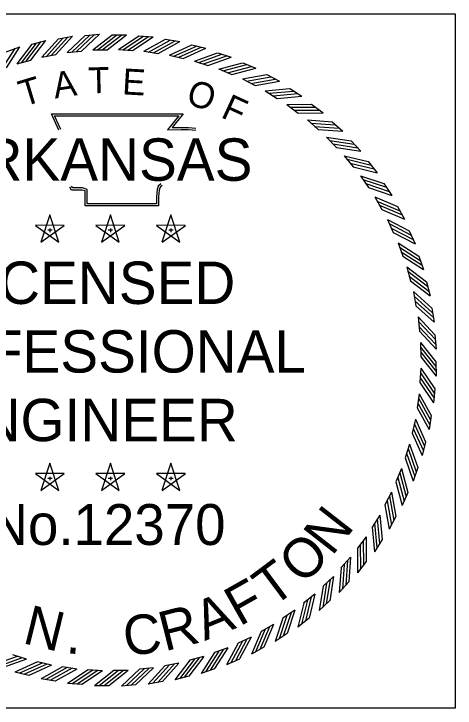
# Model space of a CAD drawing. Extents: x 0 to 1228740, y 0 to 152440.
# Drawn here: x 40.635 to 42.383, y 22.633 to 25.383 of the extents above; entities that cross this region are included whole.
import ezdxf

# ---------------------------------------------------------------- set-up
doc = ezdxf.new("R2010")
doc.units = 0
doc.layers.add('R_No Plot', color=7, linetype='Continuous')
doc.layers.add('STAMP_TNC', color=7, linetype='Continuous')

msp = doc.modelspace()

# ---------------------------------------------------------------- linework, layer by layer
at = {"layer": 'R_No Plot'}
msp.add_lwpolyline([(39.6327, 25.3826), (42.3827, 25.3826), (42.3827, 22.6326), (39.6327, 22.6326)], close=True, dxfattribs=at)
at = {"layer": 'STAMP_TNC'}
for p, q in [((40.9171, 25.2968), (40.9734, 25.302)), ((40.7068, 25.2628), (40.7615, 25.2772)), ((40.8113, 25.2841), (40.867, 25.2939)), ((41.0242, 25.2999), (41.0808, 25.2999)), ((41.1301, 25.2957), (41.1865, 25.2915)), ((41.2358, 25.282), (41.2917, 25.2732)), ((40.6045, 25.2329), (40.6578, 25.2517)), ((41.3401, 25.2595), (41.395, 25.2462)), ((40.7457, 25.2115), (40.8016, 25.2213)), ((40.8458, 25.2298), (40.9022, 25.235)), ((40.947, 25.2397), (41.0037, 25.2397)), ((41.0488, 25.2413), (41.1053, 25.2372)), ((41.1503, 25.2345), (41.2062, 25.2257)), ((41.2508, 25.2193), (41.3059, 25.2059)), ((41.4421, 25.2286), (41.4957, 25.2107)), ((40.6475, 25.1849), (40.7023, 25.1994)), ((41.3498, 25.1959), (41.4036, 25.178)), ((41.4466, 25.1644), (41.4987, 25.1421)), ((41.5412, 25.1894), (41.5932, 25.1671)), ((41.6367, 25.142), (41.6867, 25.1156)), ((41.5403, 25.125), (41.5904, 25.0984)), ((41.728, 25.087), (41.7756, 25.0565)), ((41.6306, 25.0779), (41.6783, 25.0474)), ((41.7166, 25.0236), (41.7616, 24.9892)), ((41.8144, 25.0246), (41.8594, 24.9903)), ((41.7978, 24.9624), (41.8399, 24.9244)), ((41.8954, 24.9553), (41.9374, 24.9174)), ((41.8737, 24.8947), (41.9125, 24.8533)), ((41.9704, 24.8796), (42.0091, 24.8383)), ((41.9438, 24.8209), (41.979, 24.7765)), ((42.0389, 24.7979), (42.074, 24.7536)), ((42.0075, 24.7416), (42.039, 24.6945)), ((42.1004, 24.7108), (42.1318, 24.6637)), ((42.0645, 24.6574), (42.0919, 24.6078)), ((42.1545, 24.619), (42.1819, 24.5695)), ((40.7771, 24.5864), (40.7417, 24.4779)), ((40.8123, 24.4779), (40.7772, 24.5865)), ((41.017, 24.5864), (40.9816, 24.4779)), ((41.0522, 24.4779), (41.017, 24.5865)), ((41.2568, 24.5864), (41.2215, 24.4779)), ((41.2921, 24.4779), (41.2569, 24.5865)), ((42.1143, 24.5686), (42.1375, 24.517)), ((40.8341, 24.545), (40.72, 24.5451)), ((40.7201, 24.545), (40.8124, 24.4778)), ((40.7419, 24.4779), (40.8343, 24.545)), ((40.7772, 24.5328), (40.7772, 24.5185)), ((41.074, 24.545), (40.9598, 24.5451)), ((40.9599, 24.545), (41.0522, 24.4778)), ((40.9817, 24.4779), (41.0741, 24.545)), ((41.0171, 24.5328), (41.0171, 24.5185)), ((41.3139, 24.545), (41.1997, 24.5451)), ((41.1998, 24.545), (41.2921, 24.4778)), ((41.2216, 24.4779), (41.314, 24.545)), ((41.2569, 24.5328), (41.2569, 24.5185)), ((40.769, 24.5267), (40.7859, 24.5267)), ((41.0088, 24.5267), (41.0258, 24.5267)), ((41.2487, 24.5267), (41.2657, 24.5267)), ((42.2008, 24.5229), (42.224, 24.4714)), ((42.1566, 24.4761), (42.1755, 24.4227)), ((42.2391, 24.4234), (42.2579, 24.3701)), ((42.1911, 24.3804), (42.2055, 24.3256)), ((42.269, 24.3211), (42.2833, 24.2664)), ((42.2176, 24.2822), (42.2275, 24.2264)), ((42.2903, 24.2167), (42.3001, 24.161)), ((42.2359, 24.1822), (42.2411, 24.1257)), ((42.3029, 24.1108), (42.3081, 24.0545)), ((42.2459, 24.0809), (42.2464, 24.0242)), ((42.3068, 24.0043), (42.3073, 23.9478)), ((42.2475, 23.9792), (42.2433, 23.9227)), ((42.3019, 23.8978), (42.2977, 23.8414)), ((42.2407, 23.8777), (42.2319, 23.8217)), ((42.2881, 23.7921), (42.2793, 23.7363)), ((42.2255, 23.7771), (42.2121, 23.722)), ((42.2021, 23.6781), (42.1842, 23.6243)), ((42.2657, 23.6879), (42.2523, 23.633)), ((40.7771, 23.6029), (40.7417, 23.4944)), ((40.8123, 23.4944), (40.7772, 23.603)), ((41.017, 23.6029), (40.9816, 23.4944)), ((41.0522, 23.4944), (41.017, 23.603)), ((41.2568, 23.6029), (41.2215, 23.4944)), ((41.2921, 23.4944), (41.2569, 23.603)), ((42.1706, 23.5814), (42.1483, 23.5293)), ((42.2348, 23.5859), (42.2169, 23.5322)), ((40.8341, 23.5615), (40.72, 23.5616)), ((40.7201, 23.5615), (40.8124, 23.4943)), ((40.7419, 23.4944), (40.8343, 23.5615)), ((40.769, 23.5432), (40.7859, 23.5432)), ((40.7772, 23.5493), (40.7772, 23.535)), ((41.074, 23.5615), (40.9598, 23.5616)), ((40.9599, 23.5615), (41.0522, 23.4943)), ((40.9817, 23.4944), (41.0741, 23.5615)), ((41.0088, 23.5432), (41.0258, 23.5432)), ((41.0171, 23.5493), (41.0171, 23.535)), ((41.3139, 23.5615), (41.1997, 23.5616)), ((41.1998, 23.5615), (41.2921, 23.4943)), ((41.2216, 23.4944), (41.314, 23.5615)), ((41.2487, 23.5432), (41.2657, 23.5432)), ((41.2569, 23.5493), (41.2569, 23.535)), ((42.1311, 23.4876), (42.1046, 23.4375)), ((42.1955, 23.4868), (42.1733, 23.4348)), ((42.0841, 23.3974), (42.0536, 23.3497)), ((42.1482, 23.3913), (42.1218, 23.3413)), ((42.0298, 23.3114), (41.9954, 23.2663)), ((42.0932, 23.3), (42.0627, 23.2523)), ((41.9686, 23.2301), (41.9306, 23.1881)), ((42.0308, 23.2135), (41.9965, 23.1686)), ((41.9009, 23.1542), (41.8595, 23.1155)), ((41.9615, 23.1325), (41.9236, 23.0906)), ((41.8271, 23.0842), (41.7827, 23.049)), ((41.8857, 23.0576), (41.8445, 23.0189)), ((41.7478, 23.0204), (41.7007, 22.989)), ((41.6635, 22.9635), (41.6139, 22.9361)), ((41.804, 22.9891), (41.7597, 22.9539)), ((41.5748, 22.9137), (41.5231, 22.8904)), ((41.717, 22.9276), (41.6699, 22.8962)), ((41.4823, 22.8714), (41.4289, 22.8525)), ((41.6251, 22.8735), (41.5756, 22.8461)), ((40.6843, 22.8259), (40.6305, 22.8438)), ((41.3866, 22.8368), (41.3318, 22.8224)), ((41.5291, 22.8271), (41.4776, 22.804)), ((40.7833, 22.8025), (40.7282, 22.8159)), ((41.2884, 22.8103), (41.2326, 22.8005)), ((40.6941, 22.7622), (40.6391, 22.7756)), ((40.8839, 22.7873), (40.8279, 22.7961)), ((40.9854, 22.7805), (40.9289, 22.7846)), ((41.0871, 22.782), (41.0304, 22.7815)), ((41.1883, 22.792), (41.1319, 22.7868)), ((41.4296, 22.7889), (41.3763, 22.7701)), ((40.7983, 22.7398), (40.7424, 22.7486)), ((41.3273, 22.759), (41.2726, 22.7446)), ((40.904, 22.7261), (40.8476, 22.7303)), ((41.0105, 22.7212), (40.9539, 22.7206)), ((41.117, 22.725), (41.0607, 22.7198)), ((41.2229, 22.7377), (41.1672, 22.7279))]:
    msp.add_line(p, q, dxfattribs=at)
for points in [[(40.8834, 25.2334), (40.9547, 25.3004)], [(40.9022, 25.235), (40.9735, 25.302)], [(40.9848, 25.24), (41.062, 25.3001)], [(40.684, 25.1948), (40.7433, 25.2726)], [(40.7023, 25.1994), (40.7616, 25.2772)], [(40.7457, 25.2114), (40.8112, 25.2841)], [(40.7636, 25.2144), (40.8292, 25.287)], [(40.7829, 25.2182), (40.8484, 25.2909)], [(40.8015, 25.2213), (40.867, 25.294)], [(40.8457, 25.2297), (40.9171, 25.2967)], [(40.8639, 25.2312), (40.9352, 25.2982)], [(40.947, 25.2397), (41.0241, 25.2999)], [(40.9652, 25.2395), (41.0423, 25.2997)], [(41.0037, 25.2398), (41.0808, 25.3)], [(41.0487, 25.2413), (41.1301, 25.2956)], [(41.0668, 25.2398), (41.1482, 25.2941)], [(41.0864, 25.2388), (41.1678, 25.2931)], [(41.1052, 25.2372), (41.1866, 25.2916)], [(41.1502, 25.2345), (41.2358, 25.2819)], [(41.1681, 25.2315), (41.2537, 25.2789)], [(41.1876, 25.2288), (41.2732, 25.2763)], [(41.2062, 25.2257), (41.2918, 25.2732)], [(40.5874, 25.1632), (40.6401, 25.2457)], [(40.6052, 25.1693), (40.6579, 25.2518)], [(40.6475, 25.1849), (40.7068, 25.2627)], [(40.6651, 25.1893), (40.7244, 25.2672)], [(41.2508, 25.2193), (41.34, 25.2595)], [(41.2684, 25.2148), (41.3576, 25.255)], [(41.2876, 25.2106), (41.3768, 25.2508)], [(41.3059, 25.206), (41.3951, 25.2462)], [(41.3498, 25.1959), (41.442, 25.2286)], [(41.367, 25.19), (41.4592, 25.2227)], [(41.3858, 25.1842), (41.478, 25.2169)], [(41.4036, 25.178), (41.4958, 25.2108)], [(41.4465, 25.1643), (41.5411, 25.1893)], [(41.4631, 25.157), (41.5578, 25.182)], [(41.4814, 25.1497), (41.576, 25.1747)], [(41.4986, 25.1421), (41.5932, 25.1671)], [(41.5403, 25.1249), (41.6366, 25.142)], [(41.5563, 25.1163), (41.6526, 25.1334)], [(41.5738, 25.1075), (41.6702, 25.1246)], [(41.5904, 25.0985), (41.6867, 25.1156)], [(41.6305, 25.0779), (41.7279, 25.087)], [(41.6457, 25.068), (41.7431, 25.0771)], [(41.6625, 25.0578), (41.7599, 25.0668)], [(41.6783, 25.0475), (41.7757, 25.0565)], [(41.7165, 25.0236), (41.8143, 25.0246)], [(41.7309, 25.0125), (41.8287, 25.0135)], [(41.7467, 25.0009), (41.8446, 25.0019)], [(40.8135, 24.9214), (40.7834, 24.9867), (41.3049, 24.987), (41.2613, 24.9323), (41.2968, 24.9327), (41.3264, 24.9331), (41.3559, 24.9299)], [(40.821, 24.9249), (40.7963, 24.9785), (41.2878, 24.9788), (41.244, 24.9238), (41.2969, 24.9245), (41.326, 24.9248), (41.3551, 24.9217)], [(41.7616, 24.9893), (41.8594, 24.9903)], [(41.7977, 24.9624), (41.8953, 24.9553)], [(41.8111, 24.9501), (41.9087, 24.943)], [(41.826, 24.9372), (41.9236, 24.9302)], [(41.8399, 24.9245), (41.9374, 24.9174)], [(41.8736, 24.8947), (41.9703, 24.8796)], [(41.886, 24.8813), (41.9826, 24.8662)], [(41.8997, 24.8673), (41.9964, 24.8522)], [(41.9125, 24.8534), (42.0092, 24.8383)], [(41.9437, 24.821), (42.0388, 24.7979)], [(41.9549, 24.8066), (42.05, 24.7835)], [(41.9674, 24.7915), (42.0625, 24.7684)], [(41.979, 24.7766), (42.0741, 24.7536)], [(42.0074, 24.7417), (42.1003, 24.7108)], [(42.0174, 24.7264), (42.1103, 24.6956)], [(41.2227, 24.7029), (41.2138, 24.6956), (41.2109, 24.6848), (41.2079, 24.6578), (41.2079, 24.6217), (40.9168, 24.6217), (40.9168, 24.6704), (40.9168, 24.6812), (40.905, 24.6848), (40.8636, 24.6848), (40.8562, 24.6961)], [(41.2175, 24.7093), (41.2066, 24.7004), (41.2028, 24.6864), (41.1997, 24.6582), (41.1997, 24.63), (40.9251, 24.63), (40.9251, 24.6704), (40.9251, 24.6873), (40.9062, 24.6931), (40.868, 24.6931), (40.8631, 24.7006)], [(42.0286, 24.7103), (42.1215, 24.6795)], [(42.039, 24.6946), (42.1318, 24.6637)], [(42.0644, 24.6574), (42.1544, 24.619)], [(42.0731, 24.6414), (42.1631, 24.603)], [(42.083, 24.6244), (42.173, 24.586)], [(42.0919, 24.6078), (42.1819, 24.5694)], [(42.1142, 24.5687), (42.2007, 24.523)], [(42.1215, 24.552), (42.208, 24.5063)], [(42.13, 24.5343), (42.2165, 24.4886)], [(42.1375, 24.517), (42.2241, 24.4713)], [(42.1565, 24.4762), (42.239, 24.4235)], [(42.1624, 24.459), (42.2449, 24.4063)], [(42.1694, 24.4406), (42.2519, 24.3879)], [(42.1755, 24.4228), (42.258, 24.3701)], [(42.1911, 24.3805), (42.2689, 24.3212)], [(42.1955, 24.3629), (42.2734, 24.3035)], [(42.2009, 24.344), (42.2788, 24.2847)], [(42.2056, 24.3257), (42.2834, 24.2664)], [(42.2176, 24.2823), (42.2902, 24.2168)], [(42.2206, 24.2643), (42.2932, 24.1988)], [(42.2244, 24.2451), (42.2971, 24.1795)], [(42.2275, 24.2265), (42.3002, 24.161)], [(42.2359, 24.1822), (42.3029, 24.1109)], [(42.2374, 24.1641), (42.3044, 24.0928)], [(42.2396, 24.1446), (42.3066, 24.0733)], [(42.2412, 24.1258), (42.3082, 24.0545)], [(42.2459, 24.081), (42.3068, 24.0044)], [(42.2459, 24.0628), (42.3068, 23.9862)], [(42.2465, 24.0432), (42.3074, 23.9666)], [(42.2465, 24.0243), (42.3074, 23.9477)], [(42.246, 23.9611), (42.3003, 23.8798)], [(42.2475, 23.9793), (42.3018, 23.8979)], [(42.2449, 23.9415), (42.2993, 23.8602)], [(42.2434, 23.9227), (42.2977, 23.8414)], [(42.2406, 23.8778), (42.2881, 23.7922)], [(42.2376, 23.8598), (42.2851, 23.7743)], [(42.2319, 23.8218), (42.2794, 23.7362)], [(42.235, 23.8404), (42.2825, 23.7548)], [(42.2255, 23.7772), (42.2657, 23.688)], [(42.2168, 23.7404), (42.257, 23.6512)], [(42.221, 23.7596), (42.2612, 23.6704)], [(42.2122, 23.7221), (42.2524, 23.6329)], [(42.202, 23.6782), (42.2348, 23.586)], [(42.1961, 23.661), (42.2289, 23.5688)], [(42.1842, 23.6244), (42.2169, 23.5322)], [(42.1903, 23.6422), (42.2231, 23.55)], [(42.1705, 23.5815), (42.1955, 23.4869)], [(42.1559, 23.5466), (42.1809, 23.452)], [(42.1632, 23.5648), (42.1882, 23.4702)], [(42.1483, 23.5293), (42.1733, 23.4347)], [(42.1311, 23.4877), (42.1482, 23.3914)], [(42.1225, 23.4717), (42.1396, 23.3754)], [(42.1047, 23.4376), (42.1218, 23.3412)], [(42.1137, 23.4541), (42.1307, 23.3578)], [(42.0742, 23.3823), (42.0832, 23.2848)], [(42.0841, 23.3975), (42.0932, 23.3001)], [(42.0536, 23.3497), (42.0627, 23.2523)], [(42.0639, 23.3655), (42.073, 23.2681)], [(42.0186, 23.2971), (42.0196, 23.1993)], [(42.0298, 23.3115), (42.0308, 23.2136)], [(41.9955, 23.2664), (41.9965, 23.1685)], [(42.0071, 23.2812), (42.0081, 23.1834)], [(41.9563, 23.2168), (41.9492, 23.1192)], [(41.9686, 23.2302), (41.9615, 23.1326)], [(41.9307, 23.1881), (41.9236, 23.0905)], [(41.9434, 23.202), (41.9363, 23.1044)], [(41.8735, 23.1282), (41.8583, 23.0316)], [(41.8875, 23.142), (41.8724, 23.0453)], [(41.9009, 23.1543), (41.8858, 23.0576)], [(41.8596, 23.1155), (41.8445, 23.0188)], [(41.8128, 23.0731), (41.7897, 22.978)], [(41.8271, 23.0843), (41.8041, 22.9892)], [(41.7828, 23.049), (41.7597, 22.9539)], [(41.7976, 23.0605), (41.7746, 22.9654)], [(41.7478, 23.0205), (41.717, 22.9277)], [(41.7165, 22.9993), (41.6857, 22.9065)], [(41.7326, 23.0106), (41.7018, 22.9177)], [(41.6636, 22.9636), (41.6252, 22.8736)], [(41.7007, 22.989), (41.6699, 22.8961)], [(41.614, 22.936), (41.5756, 22.846)], [(41.6306, 22.945), (41.5922, 22.855)], [(41.6476, 22.9549), (41.6092, 22.8649)], [(41.5749, 22.9138), (41.5292, 22.8272)], [(41.5232, 22.8904), (41.4775, 22.8039)], [(41.5405, 22.898), (41.4948, 22.8115)], [(41.5582, 22.9064), (41.5125, 22.8199)], [(41.4468, 22.8586), (41.3941, 22.7761)], [(41.4651, 22.8655), (41.4125, 22.7831)], [(41.4824, 22.8714), (41.4297, 22.789)], [(40.6484, 22.8376), (40.5562, 22.8049)], [(40.6672, 22.8318), (40.575, 22.7991)], [(40.6844, 22.8259), (40.5922, 22.7932)], [(41.3501, 22.827), (41.2908, 22.7492)], [(41.369, 22.8324), (41.3097, 22.7546)], [(41.3867, 22.8369), (41.3274, 22.7591)], [(41.429, 22.8525), (41.3763, 22.77)], [(40.7283, 22.8158), (40.6391, 22.7756)], [(40.7465, 22.8112), (40.6573, 22.771)], [(40.7657, 22.807), (40.6765, 22.7667)], [(40.7834, 22.8025), (40.6942, 22.7623)], [(41.2327, 22.8005), (41.1671, 22.7278)], [(41.2512, 22.8036), (41.1857, 22.7309)], [(41.2705, 22.8074), (41.205, 22.7347)], [(41.2885, 22.8104), (41.2229, 22.7377)], [(41.3319, 22.8224), (41.2726, 22.7446)], [(40.828, 22.796), (40.7424, 22.7486)], [(40.8465, 22.7929), (40.761, 22.7455)], [(40.866, 22.7903), (40.7804, 22.7429)], [(40.884, 22.7873), (40.7984, 22.7399)], [(40.9289, 22.7846), (40.8476, 22.7302)], [(40.9477, 22.783), (40.8663, 22.7287)], [(40.9673, 22.782), (40.886, 22.7277)], [(40.9855, 22.7805), (40.9041, 22.7262)], [(41.0305, 22.7815), (40.9539, 22.7206)], [(41.0493, 22.7815), (40.9727, 22.7206)], [(41.069, 22.7821), (40.9924, 22.7212)], [(41.0872, 22.7821), (41.0106, 22.7212)], [(41.132, 22.7868), (41.0607, 22.7198)], [(41.1507, 22.7883), (41.0794, 22.7213)], [(41.1703, 22.7906), (41.099, 22.7236)], [(41.1884, 22.7921), (41.1171, 22.7251)]]:
    msp.add_lwpolyline(points, dxfattribs=at)

# ---------------------------------------------------------------- texts
for s, height, rotation, p in [('T', 0.1029, 1.4789, (40.9305, 25.0675)), ('E', 0.1029, 356.672, (41.0621, 25.0643)), ('T', 0.1029, 16.9015, (40.6727, 25.0144)), ('A', 0.1029, 8.6788, (40.7976, 25.047)), ('O', 0.1029, 341.2218, (41.3119, 25.0291)), ('F', 0.1029, 335.3628, (41.4506, 24.9748)), ('N', 0.1562, 52.0417, (41.8949, 23.2317)), ('O', 0.1562, 44.0353, (41.7778, 23.117)), ('T', 0.1562, 36.7567, (41.6585, 23.0279)), ('F', 0.1562, 29.4782, (41.5287, 22.9545)), ('A', 0.1562, 22.1996, (41.3908, 22.8982)), ('N', 0.1562, 346.1707, (40.6648, 22.8912)), ('R', 0.1562, 14.1932, (41.2322, 22.857)), ('C', 0.1562, 6.5507, (41.0768, 22.8387)), ('.', 0.1562, 354.905, (40.8389, 22.8507))]:
    msp.add_text(s, height=height, rotation=rotation, dxfattribs=at).set_placement(p)
for s, height, p in [('ARKANSAS', 0.16791, (40.357, 24.7216)), ('LICENSED', 0.16791, (40.389, 24.2336)), ('PROFESSIONAL', 0.167907, (40.0452, 23.9618)), ('ENGINEER', 0.16791, (40.349, 23.6899)), ('No.12370', 0.16191, (40.5342, 23.2789))]:
    msp.add_text(s, height=height, dxfattribs=at).set_placement(p)

doc.saveas('drawing.dxf')
